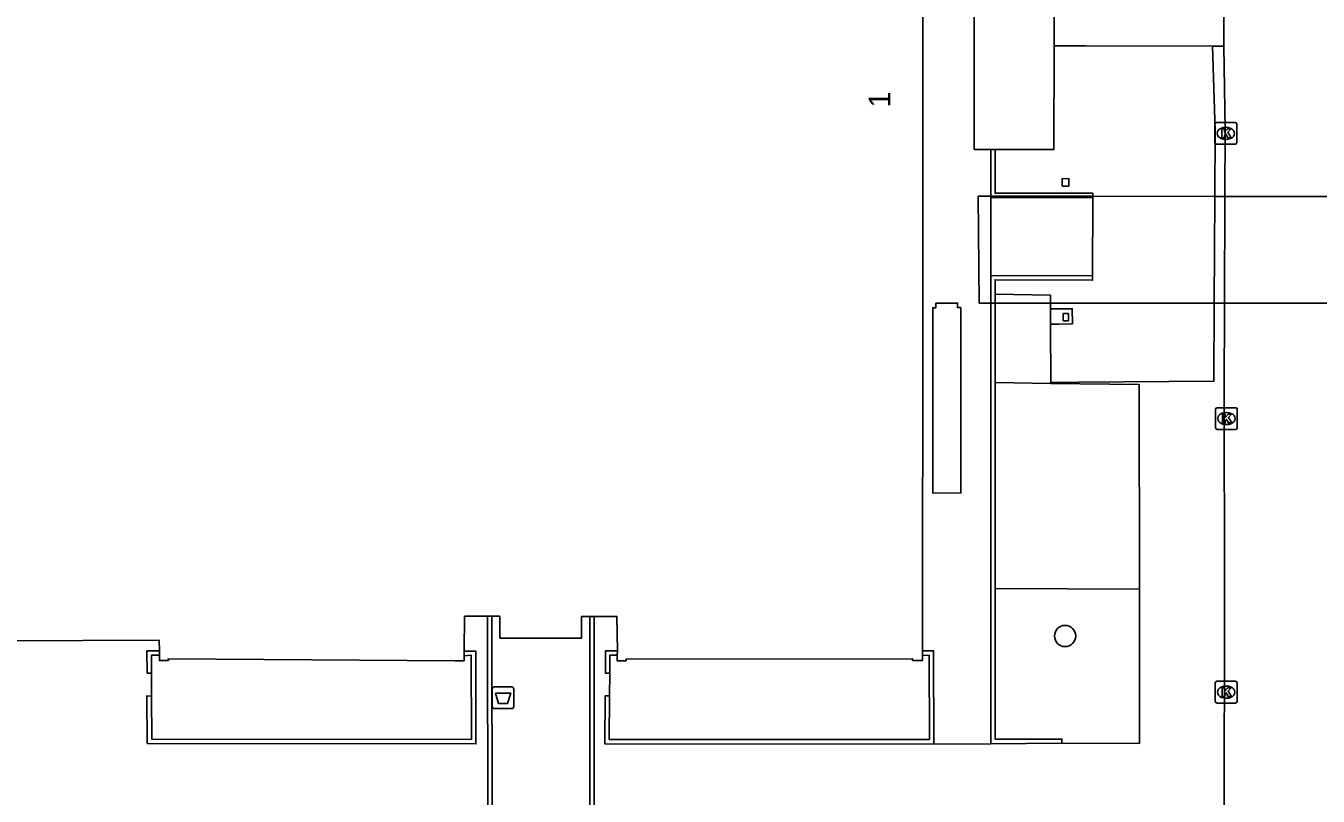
# Model space of a CAD drawing. Extents: x 161477 to 163040, y 383680 to 384868.
# Drawn here: x 161752.7 to 161812.2, y 384289.8 to 384325.3 of the extents above; entities that cross this region are included whole.
import ezdxf

# ---------------------------------------------------------------- set-up
doc = ezdxf.new("R2010")
doc.units = 0
for name, color, linetype in [('IMGEO_Afvalbak', 7, 'Continuous'), ('IMGEO_Boom', 7, 'Continuous'), ('IMGEO_Dek', 7, 'Continuous'), ('IMGEO_Kolk', 7, 'Continuous'), ('IMGEO_Muur', 7, 'Continuous'), ('IMGEO_Pand', 7, 'Continuous'), ('IMGEO_Pand_nummerreeks', 7, 'Continuous'), ('IMGEO_Parkeervlak_open', 7, 'Continuous'), ('IMGEO_Pijler', 7, 'Continuous'), ('IMGEO_Rijbaan_lokaal_open', 7, 'Continuous'), ('IMGEO_Voetpad_gesloten', 7, 'Continuous'), ('IMGEO_Voetpad_open', 7, 'Continuous')]:
    doc.layers.add(name, color=color, linetype=linetype)

msp = doc.modelspace()

# ---------------------------------------------------------------- linework, layer by layer
at = {"layer": 'IMGEO_Afvalbak'}
for p, q in [((161774.185, 384293.96), (161774.185, 384294.76)), ((161774.185, 384294.76), (161774.185, 384293.96)), ((161774.285, 384294.86), (161775.075, 384294.86)), ((161775.075, 384294.86), (161774.285, 384294.86)), ((161775.175, 384294.76), (161775.175, 384293.96)), ((161775.175, 384293.96), (161775.175, 384294.76)), ((161775.075, 384293.86), (161774.285, 384293.86)), ((161774.285, 384293.86), (161775.075, 384293.86))]:
    msp.add_line(p, q, dxfattribs=at)
msp.add_lwpolyline([(161774.328, 384294.574), (161775.032, 384294.574), (161774.883, 384294.104), (161774.477, 384294.104), (161774.328, 384294.574)], dxfattribs=at)
for centre, start, end in [((161774.285, 384294.76), 90, 180), ((161774.285, 384294.76), 90, 180), ((161775.075, 384294.76), 0, 90), ((161775.075, 384294.76), 360, 90), ((161774.285, 384293.96), 180, 270), ((161774.285, 384293.96), 180, 270), ((161775.075, 384293.96), 270, 0), ((161775.075, 384293.96), 270, 0)]:
    msp.add_arc(centre, 0.1, start, end, dxfattribs=at)
at = {"layer": 'IMGEO_Boom'}
msp.add_circle((161800.569, 384297.207), 0.489, dxfattribs=at)
at = {"layer": 'IMGEO_Dek'}
msp.add_lwpolyline([(161859.88, 384317.389), (161855.377, 384317.394), (161817.96, 384317.433), (161817.483, 384317.433), (161815.892, 384317.434), (161810.287, 384317.441), (161807.922, 384317.443), (161801.84, 384317.449), (161797.149, 384317.454), (161796.557, 384317.455), (161796.614, 384312.532), (161797.345, 384312.53), (161799.896, 384312.527), (161807.923, 384312.527), (161808.422, 384312.528), (161810.306, 384312.528), (161815.872, 384312.528), (161817.492, 384312.528), (161817.958, 384312.528), (161855.375, 384312.529), (161859.867, 384312.53)], close=True, dxfattribs=at)
at = {"layer": 'IMGEO_Kolk'}
for p, q in [((161807.469, 384319.922), (161807.469, 384320.774)), ((161807.544, 384320.848), (161808.396, 384320.848)), ((161807.957, 384320.628), (161807.982, 384320.628)), ((161808.47, 384320.774), (161808.47, 384319.922)), ((161807.98, 384320.068), (161807.955, 384320.068)), ((161808.396, 384319.848), (161807.544, 384319.848)), ((161807.499, 384306.789), (161807.499, 384307.641)), ((161807.574, 384307.715), (161808.426, 384307.715)), ((161808.5, 384307.641), (161808.5, 384306.789)), ((161808.01, 384306.935), (161807.985, 384306.935)), ((161807.987, 384307.495), (161808.012, 384307.495)), ((161808.426, 384306.715), (161807.574, 384306.715)), ((161807.485, 384294.194), (161807.485, 384295.046)), ((161807.56, 384295.12), (161808.412, 384295.12)), ((161808.486, 384295.046), (161808.486, 384294.194)), ((161807.973, 384294.9), (161807.998, 384294.9)), ((161808.412, 384294.12), (161807.56, 384294.12)), ((161807.996, 384294.34), (161807.971, 384294.34))]:
    msp.add_line(p, q, dxfattribs=at)
for points in [[(161807.469, 384319.922), (161807.469, 384320.774)], [(161807.544, 384320.848), (161808.396, 384320.848)], [(161808.47, 384320.774), (161808.47, 384319.922)], [(161807.79, 384320.548), (161807.913, 384320.548), (161807.913, 384320.397), (161808.043, 384320.548), (161808.207, 384320.548), (161808.061, 384320.397), (161808.214, 384320.148), (161808.062, 384320.148), (161807.977, 384320.312), (161807.913, 384320.245), (161807.913, 384320.148), (161807.79, 384320.148), (161807.79, 384320.548)], [(161808.396, 384319.848), (161807.544, 384319.848)], [(161807.499, 384306.789), (161807.499, 384307.641)], [(161807.574, 384307.715), (161808.426, 384307.715)], [(161808.5, 384307.641), (161808.5, 384306.789)], [(161807.82, 384307.415), (161807.943, 384307.415), (161807.943, 384307.264), (161808.073, 384307.415), (161808.237, 384307.415), (161808.091, 384307.264), (161808.244, 384307.015), (161808.092, 384307.015), (161808.007, 384307.179), (161807.943, 384307.112), (161807.943, 384307.015), (161807.82, 384307.015), (161807.82, 384307.415)], [(161808.426, 384306.715), (161807.574, 384306.715)], [(161807.485, 384294.194), (161807.485, 384295.046)], [(161807.56, 384295.12), (161808.412, 384295.12)], [(161808.486, 384295.046), (161808.486, 384294.194)], [(161807.806, 384294.82), (161807.929, 384294.82), (161807.929, 384294.669), (161808.059, 384294.82), (161808.223, 384294.82), (161808.077, 384294.669), (161808.23, 384294.42), (161808.078, 384294.42), (161807.993, 384294.584), (161807.929, 384294.517), (161807.929, 384294.42), (161807.806, 384294.42), (161807.806, 384294.82)], [(161808.412, 384294.12), (161807.56, 384294.12)]]:
    msp.add_lwpolyline(points, dxfattribs=at)
for centre, start, end in [((161807.546, 384320.772), 91.55205, 178.44795), ((161807.546, 384320.772), 91.55205, 178.44795), ((161808.394, 384320.772), 1.55205, 88.44795), ((161808.394, 384320.772), 1.55205, 88.44795), ((161807.546, 384319.924), 181.55205, 268.44795), ((161807.546, 384319.924), 181.55205, 268.44795), ((161808.394, 384319.924), 271.55205, 358.44795), ((161808.394, 384319.924), 271.55205, 358.44795), ((161807.576, 384307.639), 91.55205, 178.44795), ((161807.576, 384307.639), 91.55205, 178.44795), ((161808.424, 384307.639), 1.55205, 88.44795), ((161808.424, 384307.639), 1.55205, 88.44795), ((161807.576, 384306.791), 181.55205, 268.44795), ((161807.576, 384306.791), 181.55205, 268.44795), ((161808.424, 384306.791), 271.55205, 358.44795), ((161808.424, 384306.791), 271.55205, 358.44795), ((161807.562, 384295.044), 91.55205, 178.44795), ((161807.562, 384295.044), 91.55205, 178.44795), ((161808.41, 384295.044), 1.55205, 88.44795), ((161808.41, 384295.044), 1.55205, 88.44795), ((161807.562, 384294.196), 181.55205, 268.44795), ((161807.562, 384294.196), 181.55205, 268.44795), ((161808.41, 384294.196), 271.55205, 358.44795), ((161808.41, 384294.196), 271.55205, 358.44795)]:
    msp.add_arc(centre, 0.0765, start, end, dxfattribs=at)
for centre, major_axis, ratio, start_param, end_param in [((161807.956, 384320.348), (-0.387, 0.002), 0.722429, 4.712389, 7.853982), ((161807.981, 384320.348), (-0.39, 0.002), 0.717154, 1.570796, 4.712389), ((161807.986, 384307.215), (-0.387, 0.002), 0.722429, 4.712389, 7.853982), ((161808.011, 384307.215), (-0.39, 0.002), 0.717154, 1.570796, 4.712389), ((161807.972, 384294.62), (-0.387, 0.002), 0.722429, 4.712389, 7.853982), ((161807.997, 384294.62), (-0.39, 0.002), 0.717154, 1.570796, 4.712389)]:
    msp.add_ellipse(centre, major_axis=major_axis, ratio=ratio, start_param=start_param, end_param=end_param, dxfattribs=at)
at = {"layer": 'IMGEO_Muur'}
for points in [[(161797.143, 384319.61), (161797.149, 384317.391)], [(161797.343, 384319.61), (161797.345, 384317.591), (161801.84, 384317.591), (161801.84, 384317.449), (161801.84, 384317.391)], [(161797.149, 384317.391), (161797.789, 384317.393), (161799.92, 384317.392), (161801.84, 384317.391)], [(161801.834, 384313.784), (161797.153, 384313.81)], [(161797.153, 384313.81), (161797.153, 384312.527), (161797.154, 384292.246)], [(161801.834, 384313.784), (161801.833, 384313.584), (161797.345, 384313.606), (161797.345, 384312.94)], [(161797.345, 384312.94), (161797.345, 384312.527), (161797.345, 384308.876)], [(161797.345, 384308.876), (161797.346, 384299.385)], [(161797.346, 384299.385), (161797.347, 384292.449), (161800.419, 384292.462), (161800.42, 384292.27)], [(161773.969, 384298.113), (161773.972, 384288.153), (161752.661, 384288.163), (161752.656, 384285.632), (161747.535, 384285.643), (161747.542, 384288.157), (161742.072, 384288.161), (161742.065, 384285.641), (161736.941, 384285.639), (161736.941, 384288.16), (161716.338, 384288.178)], [(161778.673, 384298.106), (161778.675, 384288.151), (161774.172, 384288.153), (161774.169, 384298.113)], [(161804.042, 384287.932), (161804.04, 384288.14), (161800.42, 384288.142), (161778.872, 384288.151), (161778.873, 384298.105)], [(161772.886, 384296.514), (161773.426, 384296.514), (161773.43, 384292.24), (161758.292, 384292.256), (161758.277, 384294.454), (161758.495, 384294.438)], [(161758.49, 384295.495), (161758.286, 384295.498), (161758.279, 384296.528), (161758.849, 384296.526)], [(161758.851, 384296.326), (161758.481, 384296.321), (161758.49, 384295.495)], [(161758.495, 384294.438), (161758.503, 384292.459), (161773.226, 384292.439), (161773.218, 384296.315), (161772.886, 384296.294)], [(161779.592, 384295.491), (161779.392, 384295.493), (161779.399, 384296.523), (161779.949, 384296.519)], [(161779.584, 384294.451), (161779.569, 384292.446), (161794.316, 384292.437), (161794.302, 384296.322), (161794.005, 384296.308)], [(161779.938, 384296.318), (161779.598, 384296.321), (161779.592, 384295.491)], [(161794.518, 384292.229), (161794.505, 384296.529), (161794.005, 384296.528)], [(161794.518, 384292.229), (161779.368, 384292.243), (161779.384, 384294.453), (161779.584, 384294.451)], [(161797.154, 384292.246), (161800.42, 384292.27)]]:
    msp.add_lwpolyline(points, dxfattribs=at)
at = {"layer": 'IMGEO_Pand'}
for points in [[(161794.005, 384296.528), (161794.014, 384312.527), (161794.019, 384322.699), (161794.021, 384323.884), (161794.05, 384339.66)], [(161797.124, 384326.558), (161796.384, 384326.556), (161796.384, 384323.884), (161796.383, 384319.61), (161796.612, 384319.61), (161797.143, 384319.61)], [(161800.061, 384324.375), (161800.065, 384326.568), (161799.065, 384326.565)], [(161800.061, 384324.375), (161800.053, 384319.61), (161797.493, 384319.61), (161797.393, 384319.61), (161797.343, 384319.61)], [(161797.143, 384319.61), (161797.163, 384319.61), (161797.293, 384319.61), (161797.343, 384319.61)], [(161772.886, 384296.514), (161772.908, 384298.115), (161773.969, 384298.113)], [(161773.969, 384298.113), (161774.169, 384298.113)], [(161774.169, 384298.113), (161774.538, 384298.112), (161774.536, 384297.112), (161778.295, 384297.106), (161778.297, 384298.106), (161778.673, 384298.106)], [(161778.673, 384298.106), (161778.873, 384298.105)], [(161778.873, 384298.105), (161779.927, 384298.104), (161779.949, 384296.519)], [(161751.807, 384296.537), (161751.807, 384296.98), (161758.843, 384297.006), (161758.849, 384296.526)], [(161758.849, 384296.526), (161758.851, 384296.326)], [(161758.851, 384296.326), (161758.854, 384296.076), (161759.264, 384296.081), (161759.263, 384296.161), (161772.476, 384296.063), (161772.886, 384296.064), (161772.886, 384296.294)], [(161772.886, 384296.294), (161772.886, 384296.514)], [(161779.938, 384296.318), (161779.936, 384296.068), (161780.346, 384296.065), (161780.347, 384296.145), (161793.545, 384296.158), (161793.545, 384296.078), (161794.005, 384296.078), (161794.005, 384296.308)], [(161779.949, 384296.519), (161779.938, 384296.318)], [(161794.005, 384296.308), (161794.005, 384296.528)]]:
    msp.add_lwpolyline(points, dxfattribs=at)
at = {"layer": 'IMGEO_Parkeervlak_open'}
msp.add_lwpolyline([(161803.988, 384299.357), (161797.346, 384299.385)], dxfattribs=at)
at = {"layer": 'IMGEO_Pijler'}
for points in [[(161800.741, 384318.261), (161800.431, 384318.262), (161800.43, 384317.922), (161800.74, 384317.921)], [(161800.719, 384312.05), (161800.479, 384312.049), (161800.48, 384311.719), (161800.72, 384311.72)]]:
    msp.add_lwpolyline(points, close=True, dxfattribs=at)
at = {"layer": 'IMGEO_Rijbaan_lokaal_open'}
for points in [[(161807.911, 384343.752), (161807.912, 384342.77), (161807.864, 384334.408), (161807.877, 384324.354)], [(161807.877, 384324.354), (161807.935, 384320.508), (161807.925, 384317.443), (161807.908, 384312.527), (161807.894, 384308.423), (161807.907, 384299.209), (161807.894, 384288.165)]]:
    msp.add_lwpolyline(points, dxfattribs=at)
at = {"layer": 'IMGEO_Voetpad_gesloten'}
msp.add_lwpolyline([(161815.892, 384317.434), (161810.287, 384317.441), (161807.925, 384317.443), (161807.464, 384317.443), (161801.84, 384317.449), (161797.149, 384317.454), (161796.557, 384317.455), (161796.614, 384312.532), (161797.345, 384312.53), (161799.896, 384312.527), (161807.908, 384312.527), (161810.306, 384312.528), (161815.872, 384312.528)], dxfattribs=at)
at = {"layer": 'IMGEO_Voetpad_open'}
for points in [[(161799.914, 384308.879), (161801.183, 384308.889), (161807.423, 384308.935), (161807.44, 384312.527), (161807.464, 384317.443), (161807.478, 384320.481), (161807.35, 384324.357)], [(161807.35, 384324.357), (161801.506, 384324.371), (161800.061, 384324.375)], [(161807.35, 384324.357), (161807.877, 384324.354)], [(161800.74, 384317.921), (161800.43, 384317.922), (161800.431, 384318.262), (161800.741, 384318.261), (161800.74, 384317.921)], [(161797.153, 384313.81), (161797.149, 384317.391)], [(161801.84, 384317.391), (161801.834, 384313.784)], [(161797.345, 384312.94), (161799.894, 384312.896), (161799.896, 384312.527), (161799.897, 384312.266)], [(161795.765, 384312.323), (161795.615, 384312.323), (161795.615, 384312.533), (161794.619, 384312.527), (161794.619, 384312.317), (161794.469, 384312.317), (161794.474, 384303.786), (161795.77, 384303.792), (161795.765, 384312.323)], [(161799.901, 384311.566), (161800.301, 384311.568), (161800.901, 384311.571), (161800.897, 384312.271), (161800.297, 384312.268), (161799.897, 384312.266)], [(161799.897, 384312.266), (161799.901, 384311.566)], [(161800.479, 384312.049), (161800.719, 384312.05), (161800.72, 384311.72), (161800.48, 384311.719), (161800.479, 384312.049)], [(161799.901, 384311.566), (161799.914, 384308.879)], [(161797.345, 384308.876), (161799.914, 384308.823)], [(161799.914, 384308.823), (161799.914, 384308.879)], [(161803.988, 384299.357), (161803.974, 384308.789), (161799.914, 384308.823)], [(161800.42, 384292.27), (161803.998, 384292.262), (161803.988, 384299.357)], [(161758.49, 384295.495), (161758.495, 384294.438)], [(161779.592, 384295.491), (161779.584, 384294.451)], [(161797.154, 384292.246), (161794.518, 384292.229)]]:
    msp.add_lwpolyline(points, dxfattribs=at)

# ---------------------------------------------------------------- texts
at = {"layer": 'IMGEO_Pand_nummerreeks'}
msp.add_text('1', height=1, rotation=89.97156, dxfattribs=at).set_placement((161792.519, 384321.534))

doc.saveas('drawing.dxf')
